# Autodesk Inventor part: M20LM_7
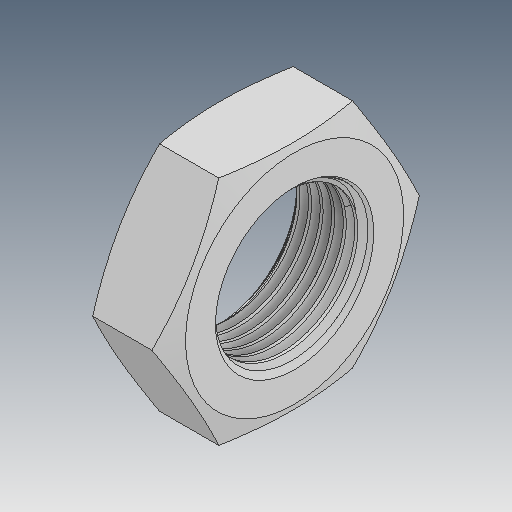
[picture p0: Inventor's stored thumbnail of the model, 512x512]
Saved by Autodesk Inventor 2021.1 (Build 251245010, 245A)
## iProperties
Created: 2019-04
Part Number: M20LM_7
Material: Ogólny
Document SubType Name: Modeling
Designer: user
Density: 1 g/cm^3
Appearance: Domyślna
Author: user
Revision Number: ÈÎºÎ
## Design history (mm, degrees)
feature "ÊäÈë1"
node "Bryła1"
